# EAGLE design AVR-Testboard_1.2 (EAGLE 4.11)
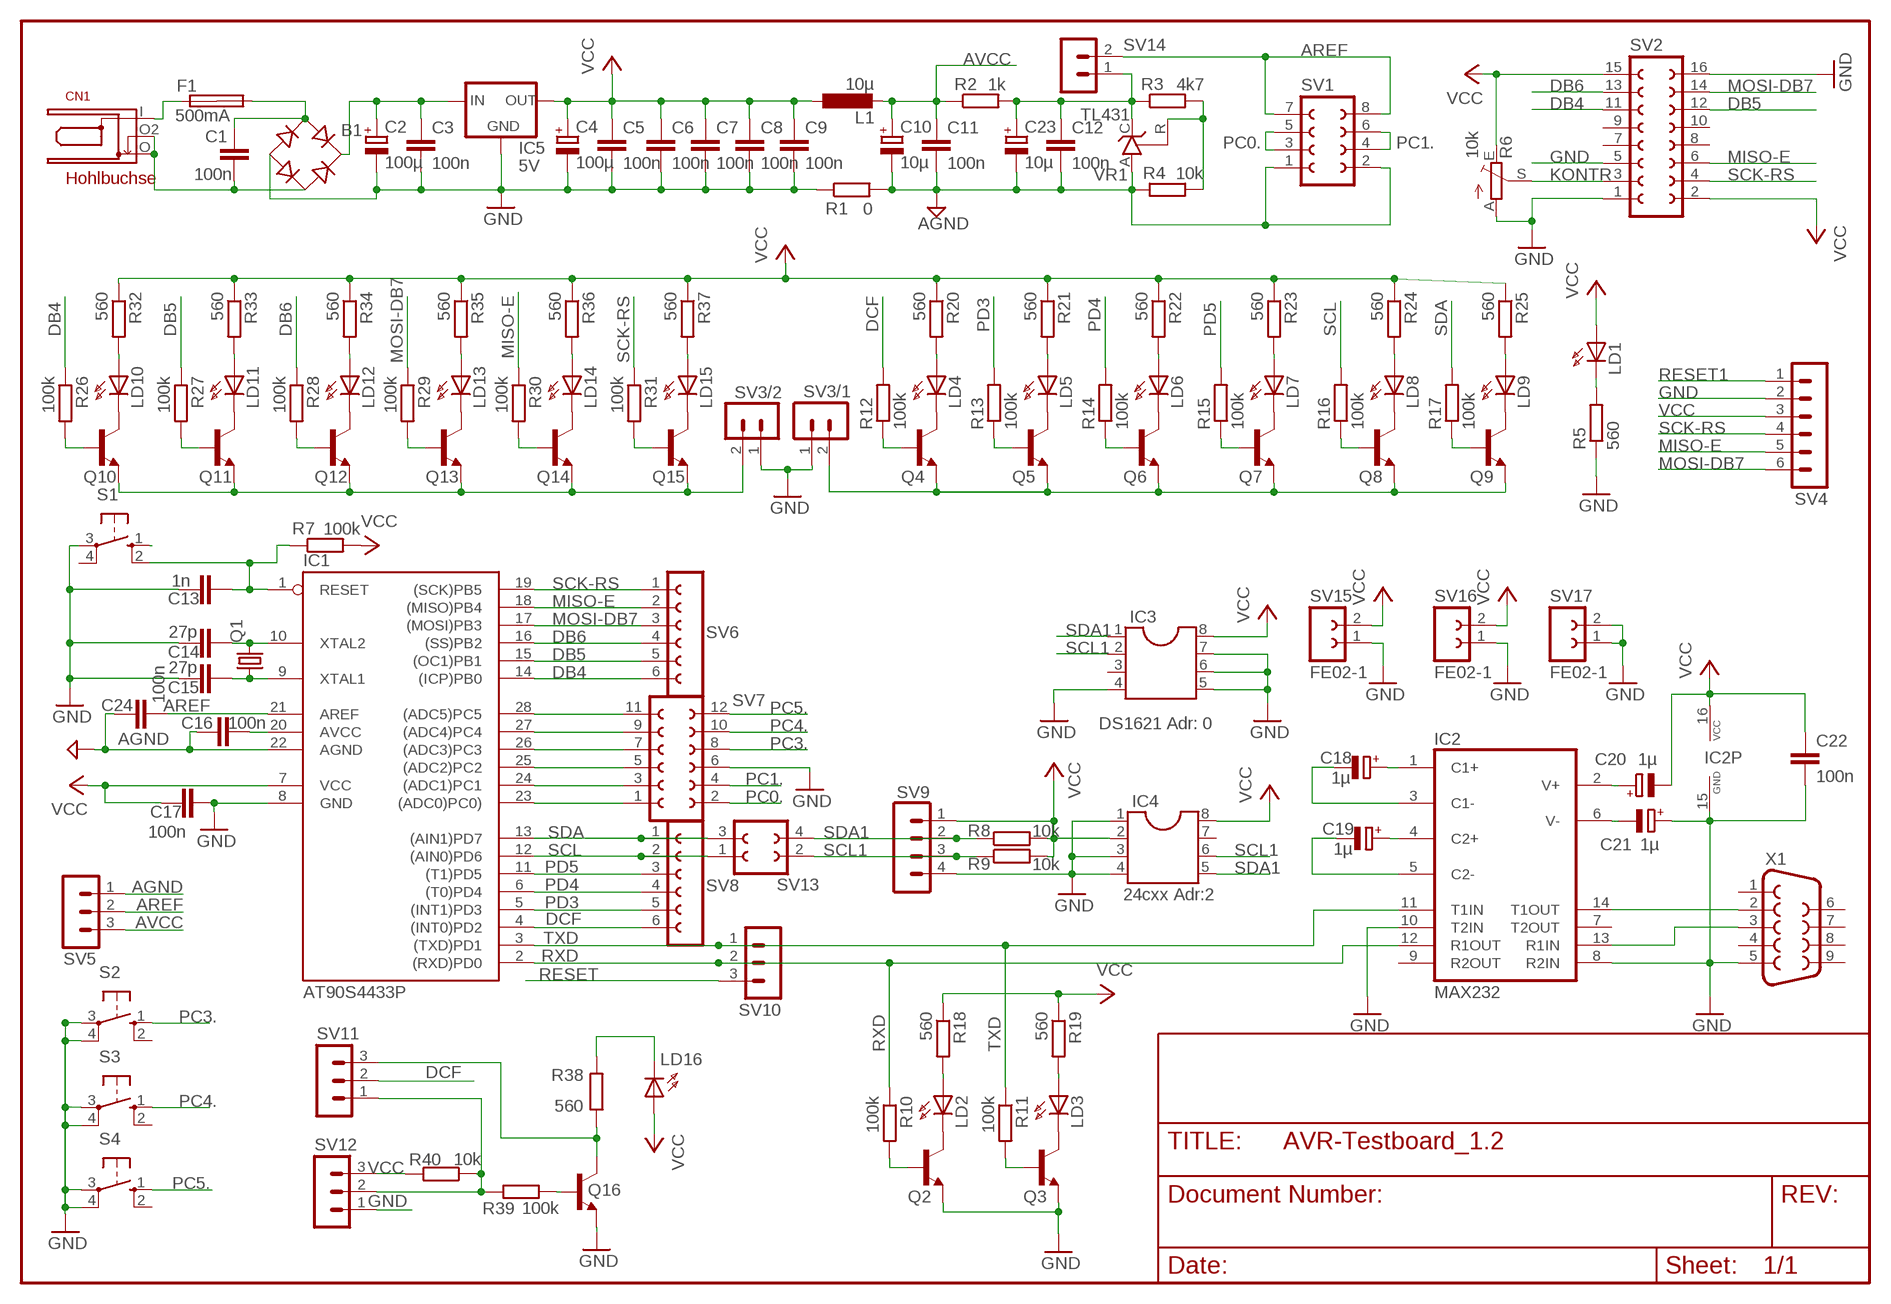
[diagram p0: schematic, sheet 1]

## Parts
B1  RB1A  [RB1A]
C1  100n  C-EU050-025X075  [C050-025X075]
C2  100µ  CPOL-EUE2.5-7  [E2,5-7]
C3  100n  C-EU050-025X075  [C050-025X075]
C4  100µ  CPOL-EUE2.5-7  [E2,5-7]
C5  100n  C-EU050-025X075  [C050-025X075]
C6  100n  C-EU050-025X075  [C050-025X075]
C7  100n  C-EU050-025X075  [C050-025X075]
C8  100n  C-EU050-025X075  [C050-025X075]
C9  100n  C-EU050-025X075  [C050-025X075]
C10  10µ  CPOL-EUE2.5-7  [E2,5-7]
C11  100n  C-EU050-025X075  [C050-025X075]
C12  100n  C-EU050-025X075  [C050-025X075]
C13  1n  C-EU050-025X075  [C050-025X075]
C14  27p  C-EU025-024X044  [C025-024X044]
C15  27p  C-EU025-024X044  [C025-024X044]
C16  100n  C-EU050-025X075  [C050-025X075]
C17  100n  C-EU050-025X075  [C050-025X075]
C18  1µ  CPOL-EUE2-5  [E2-5]
C19  1µ  CPOL-EUE2-5  [E2-5]
C20  1µ  CPOL-EUE2-5  [E2-5]
C21  1µ  CPOL-EUE2-5  [E2-5]
C22  100n  C-EU050-025X075  [C050-025X075]
C23  10µ  CPOL-EUE2.5-7  [E2,5-7]
C24  100n  C-EU050-025X075  [C050-025X075]
CN1  HOHLBUCHSE  [HOHLBUCHSE]
F1  500mA  SHK20L  [SHK20L]
IC1  AT90S4433P  [DIL28-3]
IC2  MAX232  [DIL16]
IC3  DIL8  [DIL08]
IC4  DIL8  [DIL08]
IC5  5V  78XXL  [78XXL]
L1  10µ  L-EU0204/5  [0204/5]
LD1  LED3MM  [LED3MM]
LD2  LED3MM  [LED3MM]
LD3  LED3MM  [LED3MM]
LD4  LED3MM  [LED3MM]
LD5  LED3MM  [LED3MM]
LD6  LED3MM  [LED3MM]
LD7  LED3MM  [LED3MM]
LD8  LED3MM  [LED3MM]
LD9  LED3MM  [LED3MM]
LD10  LED3MM  [LED3MM]
LD11  LED3MM  [LED3MM]
LD12  LED3MM  [LED3MM]
LD13  LED3MM  [LED3MM]
LD14  LED3MM  [LED3MM]
LD15  LED3MM  [LED3MM]
LD16  LED3MM  [LED3MM]
Q1  CRYTALHC18U-V  [HC18U-V]
Q2  BC548  [TO92-EBC]
Q3  BC548  [TO92-EBC]
Q4  BC548  [TO92-EBC]
Q5  BC548  [TO92-EBC]
Q6  BC548  [TO92-EBC]
Q7  BC548  [TO92-EBC]
Q8  BC548  [TO92-EBC]
Q9  BC548  [TO92-EBC]
Q10  BC548  [TO92-EBC]
Q11  BC548  [TO92-EBC]
Q12  BC548  [TO92-EBC]
Q13  BC548  [TO92-EBC]
Q14  BC548  [TO92-EBC]
Q15  BC548  [TO92-EBC]
Q16  BC548  [TO92-EBC]
R1  0  R-EU_0207/7  [0207/7]
R2  1k  R-EU_0204/7  [0204/7]
R3  4k7  R-EU_0204/7  [0204/7]
R4  10k  R-EU_0204/7  [0204/7]
R5  560  R-EU_0207/7  [0207/7]
R6  10k  TRIM_EU-PT10S  [PT-10S]
R7  100k  R-EU_0204/7  [0204/7]
R8  10k  R-EU_0204/7  [0204/7]
R9  10k  R-EU_0204/7  [0204/7]
R10  100k  R-EU_0204/7  [0204/7]
R11  100k  R-EU_0204/7  [0204/7]
R12  100k  R-EU_0207/15  [0207/15]
R13  100k  R-EU_0207/12  [0207/12]
R14  100k  R-EU_0207/12  [0207/12]
R15  100k  R-EU_0207/10  [0207/10]
R16  100k  R-EU_0204/7  [0204/7]
R17  100k  R-EU_0204/7  [0204/7]
R18  560  R-EU_0204/7  [0204/7]
R19  560  R-EU_0204/7  [0204/7]
R20  560  R-EU_0207/12  [0207/12]
R21  560  R-EU_0207/12  [0207/12]
R22  560  R-EU_0207/12  [0207/12]
R23  560  R-EU_0207/12  [0207/12]
R24  560  R-EU_0207/12  [0207/12]
R25  560  R-EU_0207/12  [0207/12]
R26  100k  R-EU_0207/15  [0207/15]
R27  100k  R-EU_0207/15  [0207/15]
R28  100k  R-EU_0207/15  [0207/15]
R29  100k  R-EU_0207/15  [0207/15]
R30  100k  R-EU_0207/15  [0207/15]
R31  100k  R-EU_0207/15  [0207/15]
R32  560  R-EU_0207/12  [0207/12]
R33  560  R-EU_0207/12  [0207/12]
R34  560  R-EU_0207/12  [0207/12]
R35  560  R-EU_0207/12  [0207/12]
R36  560  R-EU_0207/12  [0207/12]
R37  560  R-EU_0207/12  [0207/12]
R38  560  R-EU_0204/7  [0204/7]
R39  100k  R-EU_0204/7  [0204/7]
R40  10k  R-EU_0204/7  [0204/7]
S1  10-XX  [B3F-10XX]
S2  10-XX  [B3F-10XX]
S3  10-XX  [B3F-10XX]
S4  10-XX  [B3F-10XX]
SV1  FE04-2  [FE04-2]
SV2  FE08-2  [FE08-2]
SV3/1  MA02-1  [MA02-1]
SV3/2  MA02-1  [MA02-1]
SV4  MA06-1  [MA06-1]
SV5  MA03-1  [MA03-1]
SV6  FE06-1  [FE06]
SV7  FE06-2  [FE06-2]
SV8  FE06-1  [FE06]
SV9  MA04-1  [MA04-1]
SV10  MA03-1  [MA03-1]
SV11  MA03-1  [MA03-1]
SV12  MA03-1  [MA03-1]
SV13  FE02-2  [FE02-2]
SV14  MA02-1  [MA02-1]
SV15  FE02-1  [FE02-1]
SV16  FE02-1  [FE02-1]
SV17  FE02-1  [FE02-1]
VR1  TL431  TL431CLP  [TO92-CLP]
X1  F09H  [F09H]

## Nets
AGND: C10.- C11.2 C12.2 C16.1 C23.- C24.1 IC1.22(AGND) R1.2 R4.2 SV1.1 SV1.2 SV5.1 VR1.A
AREF: C24.2 IC1.21(AREF) SV1.7 SV1.8 SV5.2 SV14.2
AVCC: C10.+ C11.1 C16.2 IC1.20(AVCC) L1.2 R2.1 SV5.3
DB4: IC1.14((ICP)PB0) R26.1 SV2.11 SV6.6
DB5: IC1.15((OC1)PB1) R27.1 SV2.12 SV6.5
DB6: IC1.16((SS)PB2) R28.1 SV2.13 SV6.4
DCF: IC1.4((INT0)PD2) R12.2 SV8.6 SV11.2
GND: B1.- C2.- C3.2 C4.- C5.2 C6.2 C7.2 C8.2 C9.2 C13.1 C14.1 C15.1 C17.2 C21.+ C22.2 IC1.8(GND) IC2.8(R2IN) IC2.10(T2IN) IC2.15(GND) IC3.4 IC3.5 IC3.6 IC3.7 IC4.1 IC4.3 IC4.4 IC5.GND Q2.E Q3.E Q16.E R1.1 R5.1 R6.A S1.3(P) S2.3(P) S2.4(P1) S3.3(P) S3.4(P1) S4.3(P) S4.4(P1) SV2.1 SV2.5 SV2.16 SV3/1.1 SV3/2.1 SV4.2 SV7.6 SV9.4 SV12.1 SV15.1 SV16.1 SV17.1 SV17.2 X1.5
KONTR: R6.S SV2.3
MISO-E: IC1.18((MISO)PB4) R30.1 SV2.6 SV4.5 SV6.2
MOSI-DB7: IC1.17((MOSI)PB3) R29.1 SV2.14 SV4.6 SV6.3
N$1: C15.2 IC1.9(XTAL1) Q1.1
N$2: C14.2 IC1.10(XTAL2) Q1.2
N$3: CN1.I F1.2A
N$4: B1.+ C2.+ C3.1 IC5.IN
N$5: LD2.K(C) Q2.C
N$6: LD3.K(C) Q3.C
N$7: B1.AC1 C1.1 F1.1A
N$8: B1.AC2 C1.2 CN1.O CN1.O2
N$9: LD4.K(C) Q4.C
N$10: C20.+ IC2.2(V+)
N$11: C21.- IC2.6(V-)
N$12: C18.+ IC2.1(C1+)
N$13: C18.- IC2.3(C1-)
N$14: C19.+ IC2.4(C2+)
N$15: C19.- IC2.5(C2-)
N$16: LD5.K(C) Q5.C
N$17: Q16.C R38.1 SV11.3
N$18: LD6.K(C) Q6.C
N$19: LD9.K(C) Q9.C
N$20: LD8.K(C) Q8.C
N$21: LD7.K(C) Q7.C
N$22: LD2.A R18.2
N$23: LD3.A R19.2
N$24: R39.2 R40.1 SV11.1 SV12.2
N$25: LD4.A R20.2
N$26: LD5.A R21.2
N$27: LD6.A R22.2
N$28: LD7.A R23.2
N$29: LD8.A R24.2
N$30: LD9.A R25.2
N$31: LD10.K(C) Q10.C
N$32: Q4.E Q5.E Q6.E Q7.E Q8.E Q9.E SV3/1.2
N$33: LD11.K(C) Q11.C
N$34: LD12.K(C) Q12.C
N$35: LD13.K(C) Q13.C
N$36: LD14.K(C) Q14.C
N$37: LD11.A R33.2
N$38: LD12.A R34.2
N$39: LD13.A R35.2
N$40: Q10.B R26.2
N$41: Q11.B R27.2
N$42: Q12.B R28.2
N$43: Q13.B R29.2
N$44: LD14.A R36.2
N$45: LD15.K(C) Q15.C
N$46: LD15.A R37.2
N$47: Q2.B R10.2
N$48: LD16.K(C) R38.2
N$49: Q3.B R11.2
N$50: Q4.B R12.1
N$51: Q5.B R13.1
N$52: Q6.B R14.1
N$53: Q7.B R15.1
N$54: Q8.B R16.1
N$55: LD1.K(C) R5.2
N$56: Q9.B R17.1
N$57: LD10.A R32.2
N$58: C12.1 C23.+ R2.2 R3.1 SV14.1 VR1.C
N$59: Q14.B R30.2
N$60: Q15.B R31.2
N$61: Q10.E Q11.E Q12.E Q13.E Q14.E Q15.E SV3/2.2
N$62: IC2.14(T1OUT) X1.2
N$63: IC2.13(R1IN) X1.3
N$67: R3.2 R4.1 VR1.R
N$69: Q16.B R39.1
N$73: IC1.28((ADC5)PC5) SV7.11
N$74: IC1.27((ADC4)PC4) SV7.9
N$75: IC1.26((ADC3)PC3) SV7.7
N$76: IC1.25((ADC2)PC2) SV7.5
N$77: IC1.24((ADC1)PC1) SV7.3
N$78: IC1.23((ADC0)PC0)) SV7.1
PC0.: SV1.3 SV1.5 SV7.2
PC1.: SV1.4 SV1.6 SV7.4
PC3.: S2.1(S) SV7.8
PC4.: S3.1(S) SV7.10
PC5.: S4.1(S) SV7.12
PD3: IC1.5((INT1)PD3) R13.2 SV8.5
PD4: IC1.6((T0)PD4) R14.2 SV8.4
PD5: IC1.11((T1)PD5) R15.2 SV8.3
RESET: C13.2 IC1.1(RESET) R7.1 S1.2(S1) SV10.3
RESET1: S1.1(S) SV4.1
RXD: IC1.2((RXD)PD0) IC2.12(R1OUT) R10.1 SV10.2
SCK-RS: IC1.19((SCK)PB5) R31.1 SV2.4 SV4.4 SV6.1
SCL: IC1.12((AIN0)PD6) R16.2 SV8.2 SV13.1
SCL1: IC3.2 IC4.6 R9.1 SV9.3 SV13.2
SDA: IC1.13((AIN1)PD7) R17.2 SV8.1 SV13.3
SDA1: IC3.1 IC4.5 R8.1 SV9.2 SV13.4
TXD: IC1.3((TXD)PD1) IC2.11(T1IN) R11.1 SV10.1
VCC: C4.+ C5.1 C6.1 C7.1 C8.1 C9.1 C17.1 C20.- C22.1 IC1.7(VCC) IC2.16(VCC) IC3.8 IC4.2 IC4.8 IC5.OUT L1.1 LD1.A LD16.A R6.E R7.2 R8.2 R9.2 R18.1 R19.1 R20.1 R21.1 R22.1 R23.1 R24.1 R25.1 R32.1 R33.1 R34.1 R35.1 R36.1 R37.1 R40.2 SV2.2 SV2.15 SV4.3 SV9.1 SV12.3 SV15.2 SV16.2
Unconnected: F1.1B F1.2B IC2.7(T2OUT) IC2.9(R2OUT) IC3.3 IC4.7 S1.4(P1) S2.2(S1) S3.2(S1) S4.2(S1) SV2.7 SV2.8 SV2.9 SV2.10 X1.1 X1.4 X1.6 X1.7 X1.8 X1.9

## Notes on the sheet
- DS1621 Adr: 0
- 24cxx Adr:2

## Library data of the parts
B1 = rectifier:RB1A: RECTIFIER 1 A
C1 C3 C5-C9 C11-C17 C22 C24 = rcl:C-EU: CAPACITOR, European symbol
C2 C4 C10 C18-C21 C23 = rcl:CPOL-EU: POLARIZED CAPACITOR, European symbol
CN1 = Ergaenzung:HOHLBUCHSE
F1 = fuse:SHK20L: FUSE HOLDER 5 x 20 mm, SH contact, SHH1 Schukat, E1073 Buerklin
IC1 = atmel:AT90S4433: MICROCONTROLLER 4 Kbytes FLASH 128 bytes SRAM 256 bytes EEPROM UART 6-channel 10 bit ADC
IC2 = maxim:MAX232: RS232 TRANSEIVER
IC3 IC4 = dil:DIL8: SOCKET Dual In Line
IC5 = v-reg:78XXL: VOLTAGE REGULATOR
L1 = rcl:L-EU: INDUCTOR, European symbol
LD1-LD16 = led:LED: LED
Q1 = crystal:CRYTAL: CRYSTAL
Q2-Q16 = transistor-npn:BC548*: NPN Transistor
R1-R5 R7-R11 R18-R40 = rcl:R-EU_: RESISTOR, European symbol
R6 = pot:TRIM_EU-: POTENTIOMETER
R12-R17 = rcl-E:R-EU_: RESISTOR, European symbol
S1-S4 = switch-omron:10-XX: OMRON SWITCH
SV1 = con-lsta-E:FE04-2: FEMALE-PINHEADER
SV2 = con-lsta:FE08-2: FEMALE HEADER
SV3/1 SV3/2 SV14 = con-lstb-E:MA02-1
SV4 = con-lstb:MA06-1: PIN HEADER
SV5 SV10-SV12 = con-lstb:MA03-1: PIN HEADER
SV6 SV8 = con-lsta:FE06-1: FEMALE HEADER
SV7 = con-lsta:FE06-2: FEMALE HEADER
SV9 = con-lstb:MA04-1: PIN HEADER
SV13 = con-lsta-E:FE02-2: FEMALE-PINHEADER
SV15-SV17 = con-lsta-E:FE02-1: FEMALE-PINHEAD
VR1 = v-reg:TL431CLP: VOLTAGE REGULATOR
X1 = con-subd:F09: SUB-D

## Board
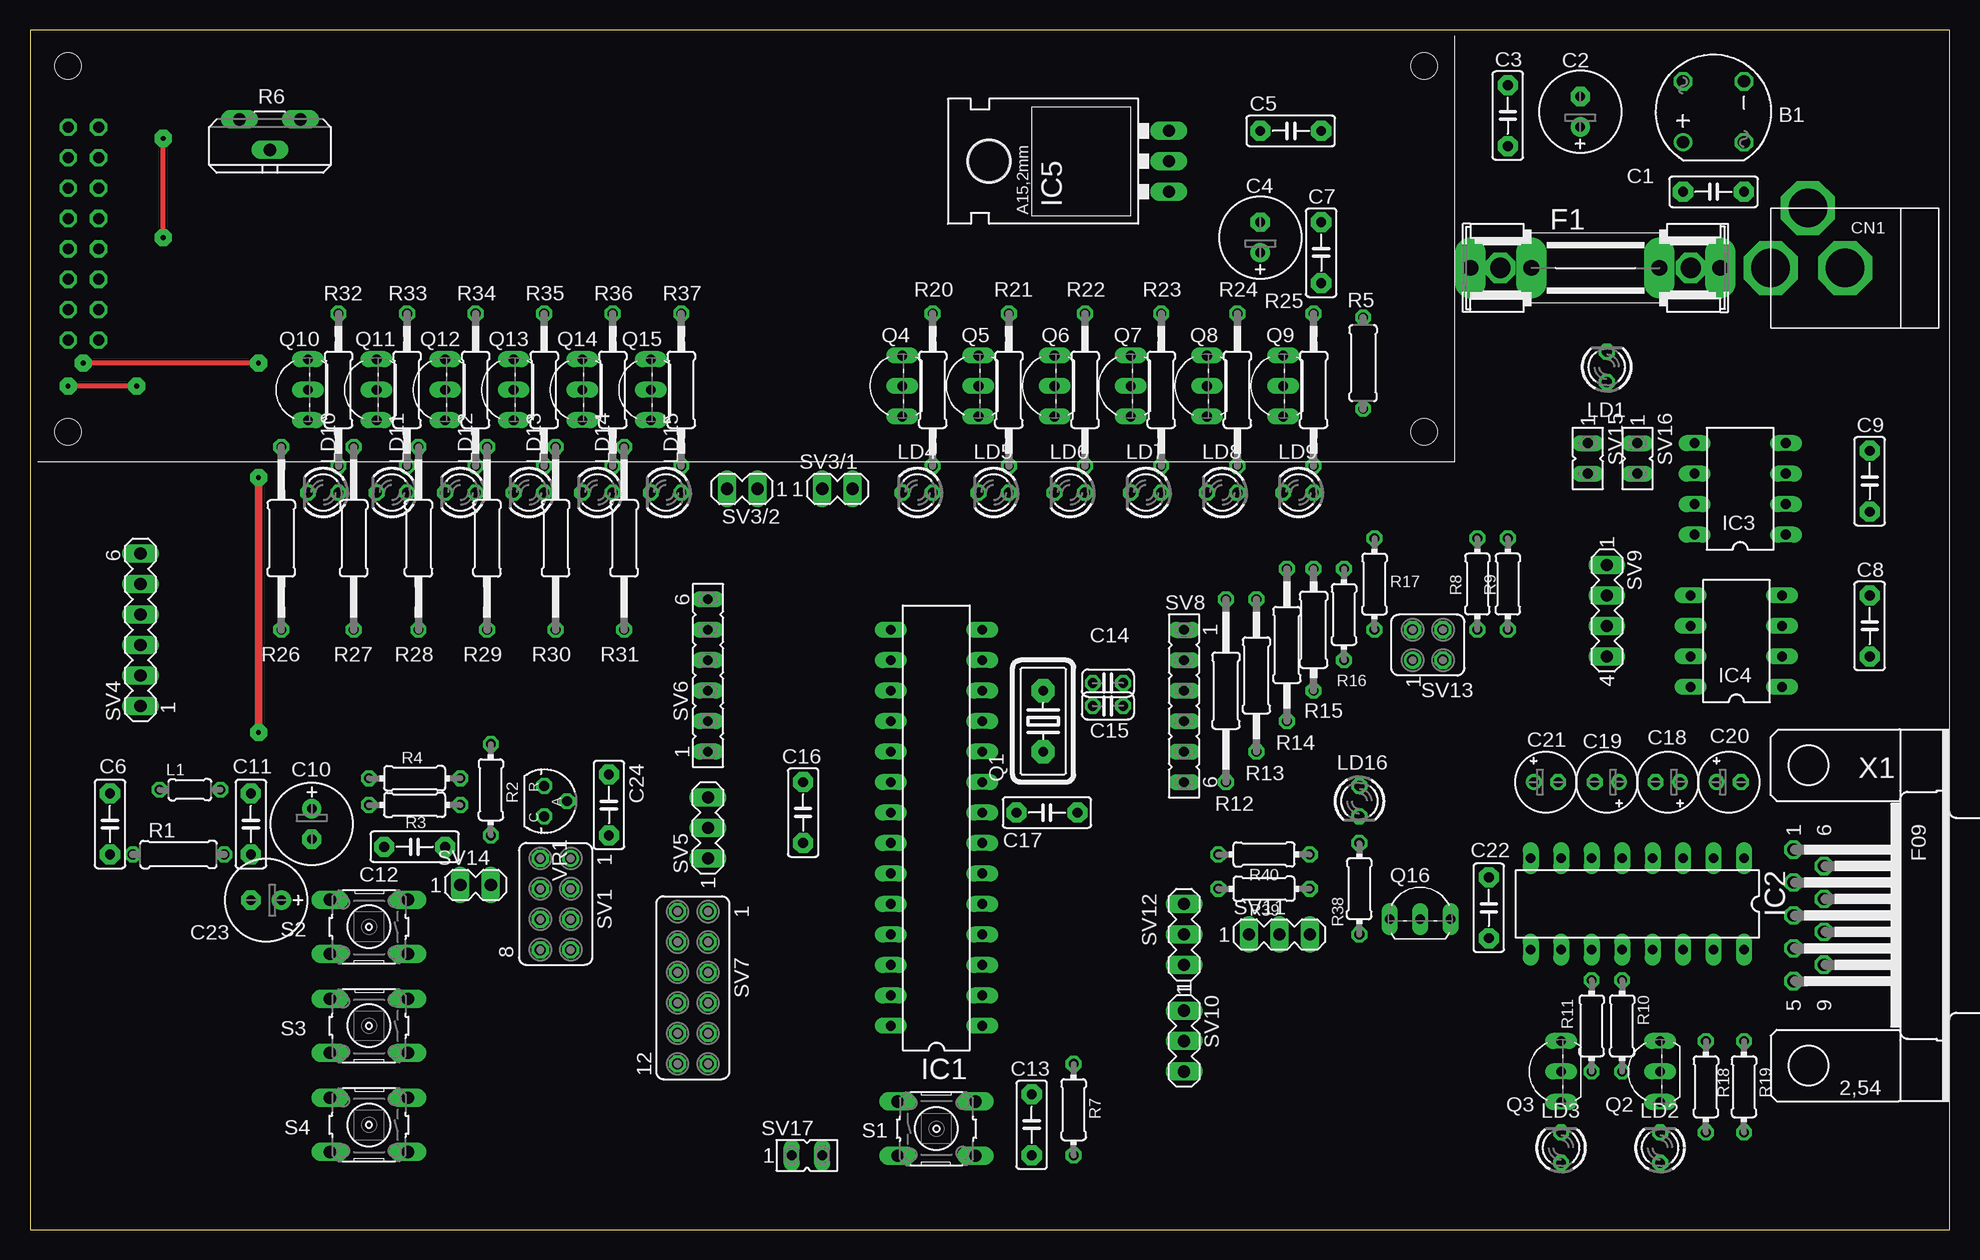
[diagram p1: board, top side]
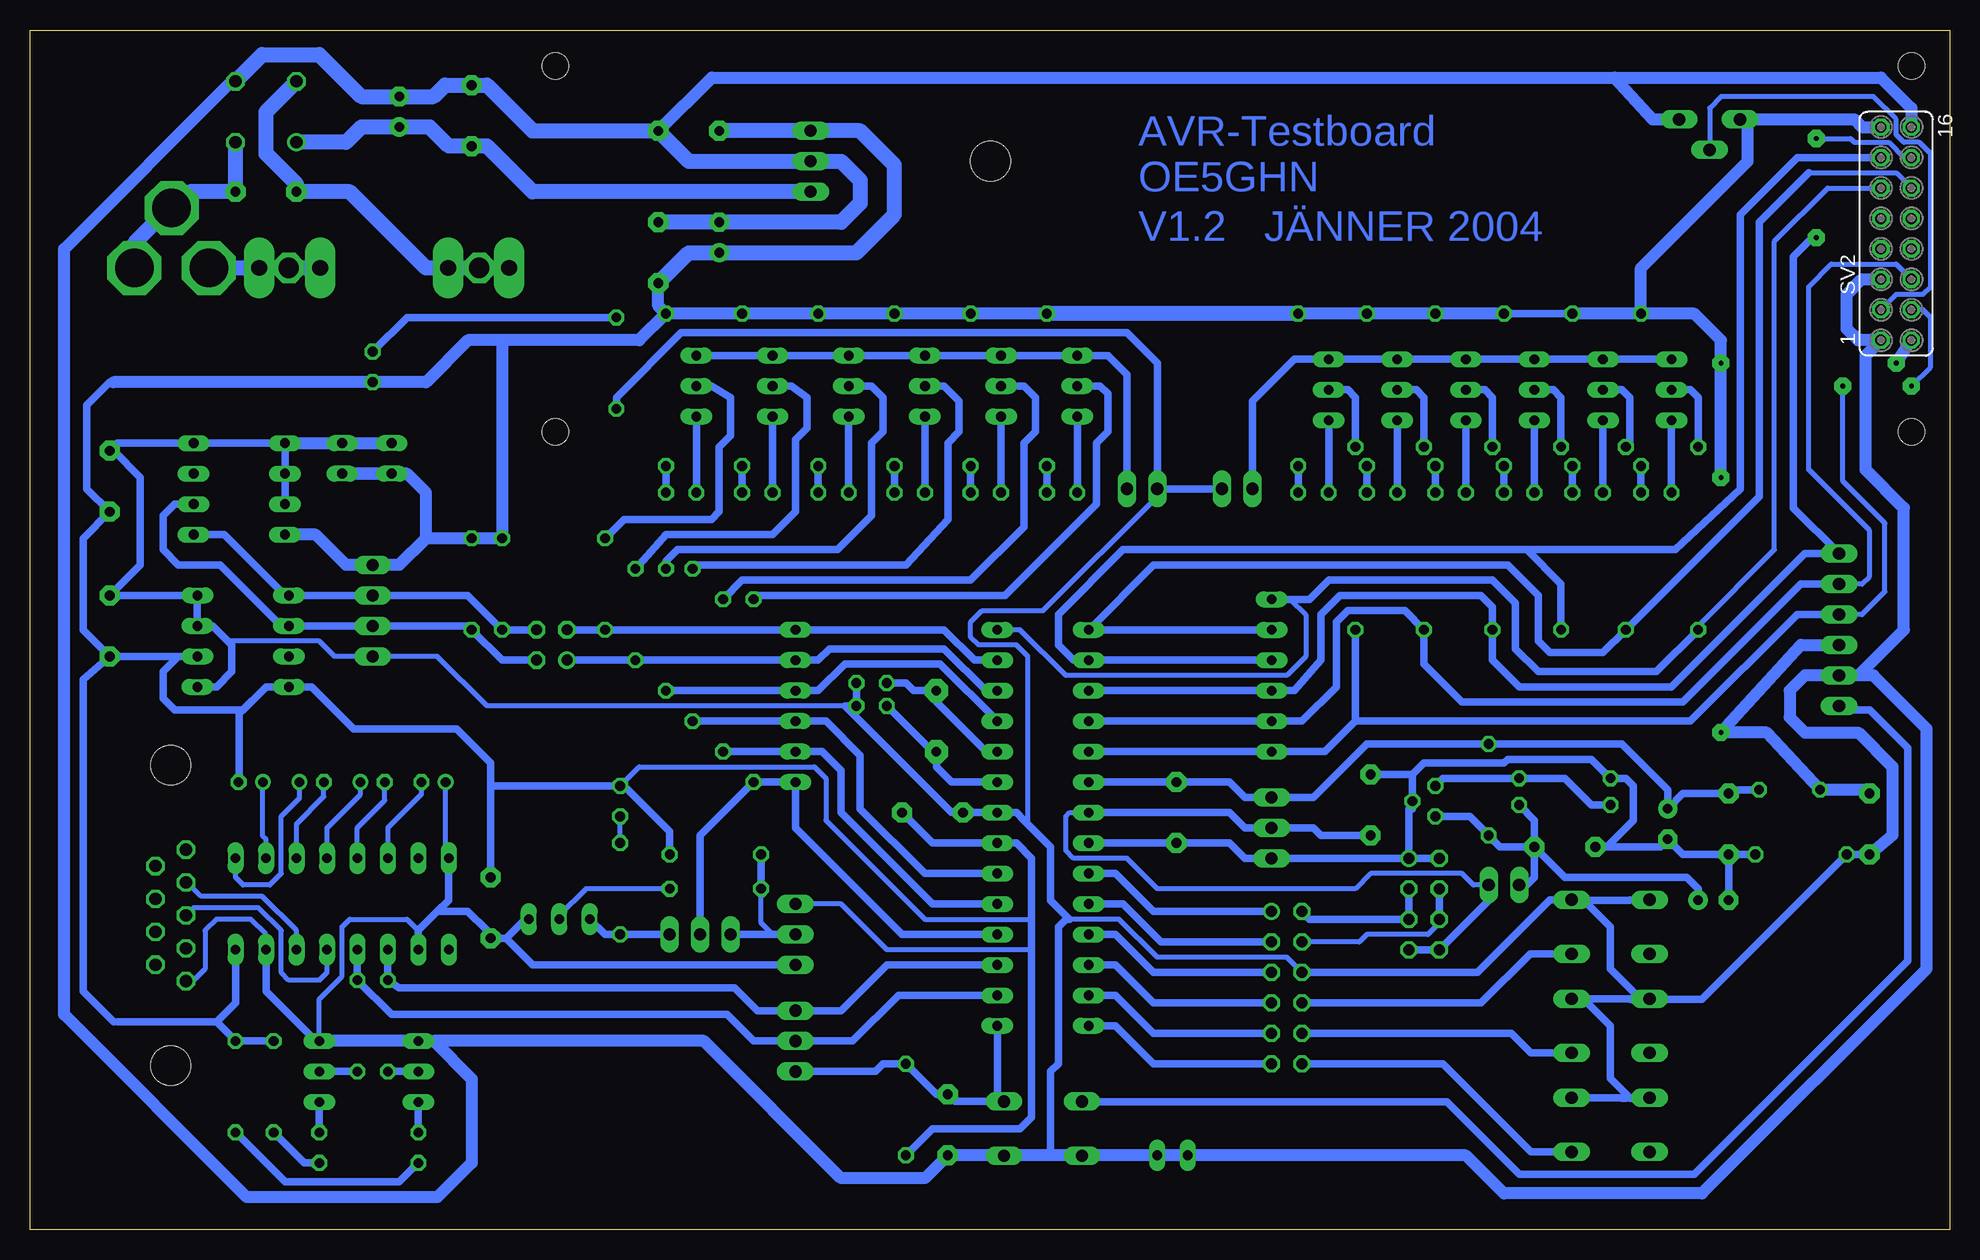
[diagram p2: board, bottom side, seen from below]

Size 160 x 100 mm. Coordinates in mm from the lower left corner, seen from the top.
Outline: 0,0 160,0 160,100 0,100 0,0
Copper layers (1*16): Top 0.035mm / dielectric 1.5mm / Bottom 0.035mm
Design rules "default": minimum track width 16mil, minimum drill 24mil, track to track 8mil, track to pad 8mil, pad to pad 8mil, via to via 8mil, smd to smd 8mil, copper to edge 40mil, drill to drill 20mil, minimum pad ring 10mil, minimum via ring 8mil, stop-mask expansion 4mil, vias tented up to drill 0mil, thermal gap 10mil
Holes 2.18 mm at 3.17,66.51 116.2,66.51 116.2,96.99 3.17,96.99

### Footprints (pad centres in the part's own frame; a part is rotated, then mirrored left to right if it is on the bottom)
RB1A = drill 1.016 round: + -2.54,2.54 | drill 1.016 octagon: - 2.54,-2.54; AC1 2.54,2.54; AC2 -2.54,-2.54
C050-025X075 = drill 0.813 pad 1.676 octagon: 1 -2.54,0; 2 2.54,0
E2,5-7 = drill 0.813 pad 1.6 round: + -1.27,0 | drill 0.813 pad 1.6 octagon: - 1.27,0
C025-024X044 = drill 0.813 octagon: 1 -1.27,0; 2 1.27,0
E2-5 = drill 0.813 pad 1.27 round: + -1.016,0 | drill 0.813 pad 1.27 octagon: - 1.016,0
HOHLBUCHSE = drill 3.2 pad 4.5 octagon: I 0,0; O 6.2,0; O2 3.1,5
SHK20L = drill 1.321 pad 2.54 long: 1A -10.414,0; 1B -5.334,0; 2A 10.414,0; 2B 5.334,0
DIL28-3 = drill 0.813 long: 1 -16.51,-3.81; 2 -13.97,-3.81; 3 -11.43,-3.81; 4 -8.89,-3.81; 5 -6.35,-3.81; 6 -3.81,-3.81; 7 -1.27,-3.81; 8 1.27,-3.81; 9 3.81,-3.81; 10 6.35,-3.81; 11 8.89,-3.81; 12 11.43,-3.81; 13 13.97,-3.81; 14 16.51,-3.81; 15 16.51,3.81; 16 13.97,3.81; 17 11.43,3.81; 18 8.89,3.81; 19 6.35,3.81; 20 3.81,3.81; 21 1.27,3.81; 22 -1.27,3.81; 23 -3.81,3.81; 24 -6.35,3.81; 25 -8.89,3.81; 26 -11.43,3.81; 27 -13.97,3.81; 28 -16.51,3.81
DIL16 = drill 0.813 long: 1 -8.89,-3.81; 2 -6.35,-3.81; 3 -3.81,-3.81; 4 -1.27,-3.81; 5 1.27,-3.81; 6 3.81,-3.81; 7 6.35,-3.81; 8 8.89,-3.81; 9 8.89,3.81; 10 6.35,3.81; 11 3.81,3.81; 12 1.27,3.81; 13 -1.27,3.81; 14 -3.81,3.81; 15 -6.35,3.81; 16 -8.89,3.81
DIL08 = drill 0.813 long: 1 -3.81,-3.81; 2 -1.27,-3.81; 3 1.27,-3.81; 4 3.81,-3.81; 5 3.81,3.81; 6 1.27,3.81; 7 -1.27,3.81; 8 -3.81,3.81
78XXL = drill 1.016 long: GND 0,-3.81; IN -2.54,-3.81; OUT 2.54,-3.81 | hole 3.302: 0,11.176
0204/5 = drill 0.813 octagon: 1 -2.54,0; 2 2.54,0
LED3MM = drill 0.813 octagon: A -1.27,0; K 1.27,0
HC18U-V = drill 0.813 pad 1.93 octagon: 1 -2.54,0; 2 2.54,0
TO92-EBC = drill 0.813 long: B 0,-1.27; C -2.54,-1.27; E 2.54,-1.27
0207/7 = drill 0.813 octagon: 1 -3.81,0; 2 3.81,0
0204/7 = drill 0.813 octagon: 1 -3.81,0; 2 3.81,0
PT-10S = drill 1.016 long: A -2.54,-1.27; E 2.54,-1.27; S 0,1.27
0207/15 = drill 0.813 octagon: 1 -7.62,0; 2 7.62,0
0207/12 = drill 0.813 octagon: 1 -6.35,0; 2 6.35,0
0207/10 = drill 0.813 octagon: 1 -5.08,0; 2 5.08,0
B3F-10XX = drill 1.016 long: 1 -3.251,2.261; 2 3.251,2.261; 3 -3.251,-2.261; 4 3.251,-2.261
FE04-2 = drill 0.914 round: 1 -3.81,1.27 | drill 0.914 octagon: 2 -3.81,-1.27; 3 -1.27,1.27; 4 -1.27,-1.27; 5 1.27,1.27; 6 1.27,-1.27; 7 3.81,1.27; 8 3.81,-1.27
FE08-2 = drill 0.914 octagon: 1 -8.89,1.27; 2 -8.89,-1.27; 3 -6.35,1.27; 4 -6.35,-1.27; 5 -3.81,1.27; 6 -3.81,-1.27; 7 -1.27,1.27; 8 -1.27,-1.27; 9 1.27,1.27; 10 1.27,-1.27; 11 3.81,1.27; 12 3.81,-1.27; 13 6.35,1.27; 14 6.35,-1.27; 15 8.89,1.27; 16 8.89,-1.27
MA02-1 = drill 1.016 long: 1 -1.27,0; 2 1.27,0
MA06-1 = drill 1.016 long: 1 -6.35,0; 2 -3.81,0; 3 -1.27,0; 4 1.27,0; 5 3.81,0; 6 6.35,0
MA03-1 = drill 1.016 long: 1 -2.54,0; 2 0,0; 3 2.54,0
FE06 = drill 0.813 long: 1 -6.35,0; 2 -3.81,0; 3 -1.27,0; 4 1.27,0; 5 3.81,0; 6 6.35,0
FE06-2 = drill 0.914 round: 1 -6.35,1.27 | drill 0.914 octagon: 2 -6.35,-1.27; 3 -3.81,1.27; 4 -3.81,-1.27; 5 -1.27,1.27; 6 -1.27,-1.27; 7 1.27,1.27; 8 1.27,-1.27; 9 3.81,1.27; 10 3.81,-1.27; 11 6.35,1.27; 12 6.35,-1.27
MA04-1 = drill 1.016 long: 1 -3.81,0; 2 -1.27,0; 3 1.27,0; 4 3.81,0
FE02-2 = drill 0.914 round: 1 -1.27,1.27 | drill 0.914 octagon: 2 -1.27,-1.27; 3 1.27,1.27; 4 1.27,-1.27
FE02-1 = drill 0.813 long: 1 -1.27,0; 2 1.27,0
TO92-CLP = drill 0.813 octagon: A 0,1.905; C 1.27,0; R -1.27,0
F09H = drill 1.016 octagon: 1 -5.486,-1.27; 2 -2.743,-1.27; 3 0,-1.27; 4 2.743,-1.27; 5 5.486,-1.27; 6 -4.115,1.27; 7 -1.372,1.27; 8 1.372,1.27; 9 4.115,1.27 | hole 3.302: -12.522,0; 12.522,0

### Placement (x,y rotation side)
B1  140.33,93.18 90 top
C1  140.33,86.51 0 top
C2  129.22,93.18 90 top
C3  123.19,92.86 90 top
C4  102.55,82.7 90 top
C5  105.09,91.59 0 top
C6  6.66,33.81 270 top
C7  107.63,81.43 90 top
C8  153.35,50.32 90 top
C9  153.35,62.38 90 top
C10  23.49,33.81 270 top
C11  18.41,33.81 270 top
C12  32.06,31.9 180 top
C13  83.5,8.73 90 top
C14  89.85,45.55 180 top
C15  89.85,43.65 180 top
C16  64.45,34.76 90 top
C17  84.77,34.76 180 top
C18  136.52,37.3 180 top
C19  131.44,37.3 180 top
C20  141.6,37.3 0 top
C21  126.36,37.3 0 top
C22  121.6,26.82 270 top
C23  19.68,27.46 180 top
C24  48.26,35.39 270 top
CN1  145.09,80.16 0 top
F1  130.49,80.16 0 top
IC1  75.56,33.49 90 top
IC2  133.98,27.14 180 top
IC3  142.55,61.75 90 top
IC4  142.23,49.05 90 top
IC5  91.12,89.05 90 top
L1  13.33,36.66 0 top
LD1  131.44,71.91 90 top
LD2  135.88,6.82 90 top
LD3  127.63,6.82 90 top
LD4  73.97,61.43 180 top
LD5  80.32,61.43 180 top
LD6  86.67,61.43 180 top
LD7  93.02,61.43 180 top
LD8  99.37,61.43 180 top
LD9  105.72,61.43 180 top
LD10  24.44,61.43 180 top
LD11  30.16,61.43 180 top
LD12  35.87,61.43 180 top
LD13  41.59,61.43 180 top
LD14  47.3,61.43 180 top
LD15  53.02,61.43 180 top
LD16  110.8,35.71 270 top
Q1  84.45,42.38 90 top
Q2  134.62,13.17 90 top
Q3  126.36,13.17 90 top
Q4  71.43,70.32 90 top
Q5  77.78,70.32 90 top
Q6  84.13,70.32 90 top
Q7  90.48,70.32 90 top
Q8  96.83,70.32 90 top
Q9  103.18,70.32 90 top
Q10  21.9,70 90 top
Q11  27.62,70 90 top
Q12  33.33,70 90 top
Q13  39.05,70 90 top
Q14  44.76,70 90 top
Q15  50.48,70 90 top
Q16  115.88,27.14 0 top
R1  12.38,31.27 0 top
R2  38.41,36.66 270 top
R3  32.06,35.39 180 top
R4  32.06,37.62 180 top
R5  111.12,72.22 90 top
R6  20,91.28 180 top
R7  86.99,10 270 top
R8  120.64,53.81 90 top
R9  123.19,53.81 90 top
R10  132.71,16.98 270 top
R11  130.17,16.98 270 top
R12  99.69,44.92 270 top
R13  102.23,46.19 270 top
R14  104.77,48.73 270 top
R15  106.99,50 270 top
R16  109.53,51.27 270 top
R17  112.07,53.81 270 top
R18  139.69,11.9 270 top
R19  142.87,11.9 270 top
R20  75.24,70 270 top
R21  81.59,70 270 top
R22  87.94,70 270 top
R23  94.29,70 270 top
R24  100.64,70 270 top
R25  106.99,70 270 top
R26  20.95,57.62 90 top
R27  26.98,57.62 90 top
R28  32.38,57.62 90 top
R29  38.1,57.62 90 top
R30  43.81,57.62 90 top
R31  49.53,57.62 90 top
R32  25.71,70 270 top
R33  31.43,70 270 top
R34  37.14,70 270 top
R35  42.86,70 270 top
R36  48.57,70 270 top
R37  54.29,70 270 top
R38  110.8,28.41 90 top
R39  102.86,28.41 180 top
R40  102.86,31.27 0 top
S1  75.56,8.41 0 top
S2  28.25,25.23 180 top
S3  28.25,16.98 180 top
S4  28.25,8.73 180 top
SV1  43.81,27.14 270 top
SV2  4.44,83.02 90 bottom
SV3/1  67.3,61.75 0 top
SV3/2  59.37,61.75 180 top
SV4  9.2,50 90 top
SV5  56.51,33.49 90 top
SV6  56.51,46.19 90 top
SV7  55.24,20.15 270 top
SV8  96.2,43.65 270 top
SV9  131.44,51.59 270 top
SV10  96.2,15.71 270 top
SV11  104.13,24.6 0 top
SV12  96.2,24.6 90 top
SV13  116.52,48.73 90 top
SV14  37.14,28.73 0 top
SV15  129.85,64.29 270 top
SV16  133.98,64.29 270 top
SV17  64.77,6.18 0 top
VR1  42.86,35.71 270 top
X1  148.27,26.19 270 top

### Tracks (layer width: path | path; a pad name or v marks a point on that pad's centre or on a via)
AGND
  Bottom 0.61: SV1.1 SV1.2 | C11.2 R1.2 | C11.2 22.22,31.27 C10.- 24.12,31.9 C12.2 28.57,31.9 26.35,34.12 26.35,36.98 26.98,37.62 R4.2 29.84,39.2 36.83,39.2 37.14,38.89 43.81,38.89 44.76,37.94 | 44.76,37.94 VR1.A 44.76,35.08 45.08,35.08 SV1.1 | IC1.22 C16.1 60,32.22 58.73,30.95 SV5.1 SV1.1 | C23.- C11.2 | 44.76,37.94 C24.1
AREF
  Bottom 0.406: IC1.21 73.34,34.76 73.66,34.44 73.66,31.58 73.02,30.95 68.57,30.95 66.03,28.41 49.53,28.41 48.26,29.68 40.64,29.68 39.68,28.73 SV14.2
  Bottom 0.61: IC1.21 60,34.76 58.73,33.49 SV5.2 53.02,33.49 52.38,32.85 C24.2 | SV1.7 SV1.8 38.41,27.46 SV14.2
AVCC
  Bottom 0.61: 56.83,36.03 58.73,36.03 60,37.3 C16.2 IC1.20 | L1.2 18.09,36.66 C11.1 22.22,36.35 C10.+ 23.49,36.66 27.3,40.48 R2.1 48.57,40.48 53.02,36.03 56.83,36.03 | 56.83,36.03 SV5.3
DB4
  Bottom 0.406: IC1.14 77.46,50 73.66,46.19 55.24,46.19 53.65,47.78 53.65,51.27 54.92,52.54 SV6.6 | 20.95,50.32 14.6,56.67 14.6,82.39 10.16,86.83 SV2.11
  Bottom 0.61: SV6.6 53.34,52.54 51.75,54.13 38.1,54.13 36.19,52.22 36.19,48.41 34.29,46.51 24.44,46.51 R26.1 20.95,50.32
DB5
  Bottom 0.406: 11.74,88.1 4.44,88.1 SV2.12
  Bottom 0.61: SV6.5 IC1.15 66.35,55.4 36.83,55.4 34.29,52.86 34.29,49.05 33.33,48.09 28.89,48.09 R27.1 15.87,61.11 15.87,83.97 11.74,88.1
DB6
  Bottom 0.61: 35.24,56.67 32.38,53.81 R28.1 | 35.24,56.67 22.86,56.67 17.46,61.75 17.46,84.61 12.7,89.37 SV2.13 | 35.24,56.67 68.89,56.67 74.29,51.27 74.29,48.73 73.02,47.46 IC1.16 SV6.4
DCF
  Bottom 0.61: IC1.4 87.31,24.6 96.2,33.49 SV8.6 R12.2 104.13,32.85 SV11.2
GND
  Bottom 0.406: SV4.2 7.62,46.19 | 73.34,25.87 69.21,25.87 66.03,22.7 55.24,22.7 SV7.6 | IC2.8 125.09,31.27 125.34,31.52 C21.+ | IC2.15 140.33,24.6 141.6,25.87 144.46,25.87 145.41,24.92 145.41,21.74 146.45,20.7 X1.5 | 127.63,24.92 128.58,25.87 133.34,25.87 133.98,25.23 133.98,21.11 135.88,19.2 Q2.E | 143.5,49.05 135.88,49.05 134.62,47.78 SV9.4 126.04,47.78 121.91,43.65 92.07,43.65 | 66.03,61.11 75.56,51.59 80.64,51.59 81.59,50.63 81.59,49.37 80.96,48.73 77.78,48.73 76.83,47.78 76.83,34.12 77.15,34.12 | 143.19,95.72 B1.-
  Bottom 0.61: IC4.1 144.46,45.24 143.19,46.51 143.19,48.73 143.5,49.05 144.78,50.32 IC4.3 146.36,50.32 146.04,50.63 IC4.4 C8.2 150.81,55.4 150.81,62.7 153.03,64.92 C9.2 152.71,65.56 IC3.4 | SV12.1 118.1,22.06 120.33,24.28 | 120.33,24.28 C22.2 121.91,23.96 121.91,24.92 123.5,26.5 126.04,26.5 | R5.1 111.12,69.37 105.72,74.77 68.57,74.77 66.03,72.22 SV3/1.1 | 89.21,40.79 83.18,34.76 C17.2 IC1.8 77.78,34.76 77.15,34.12 74.92,31.9 74.92,27.46 73.34,25.87 73.66,25.87 74.29,25.23 74.29,13.81 74.92,13.17 74.92,6.18 | 89.21,40.79 89.66,41.24 | 126.04,26.5 127.63,24.92 IC2.10 127.31,23.01 | IC2.8 125.09,27.46 126.04,26.5 | Q2.E 136.2,15.71 140.33,19.84 IC2.15 | 89.21,40.79 92.07,43.65 C15.1 C14.1 | C6.2 R1.1 20.63,19.2 25.71,19.2 | IC3.7 IC3.6 IC3.5 IC3.4 | IC3.4 146.68,65.56 | 126.36,15.71 Q3.E | S2.4 26.63,27.5 26.66,27.46 30.47,27.46 | Q16.E 118.74,25.87 120.33,24.28 | C13.1 83.46,6.15 | S3.3 32.42,19.24 | 26.66,10.99 26.94,10.99 26.98,10.95 27.3,10.95 | 26.63,10.99 S4.4 | 26.63,10.99 26.66,10.99 | S2.3 32.74,27.5 | 26.66,19.2 26.63,19.24 | 26.66,10.99 S4.3 | 26.66,10.95 26.35,10.95 | 26.66,19.2 26.66,19.24 | S2.3 33.29,27.5 39.37,21.42 SV7.6 | 73.69,6.15 S1.3 72.35,6.15 72.38,6.18 | 26.66,10.99 26.66,10.95 | 26.63,10.99 26.66,10.95 | SV3/1.1 66.35,61.75 | 66.03,61.11 SV3/1.1 | SV3/1.1 SV3/2.1 | 26.66,19.2 26.35,19.2 26.39,19.24 S3.3 | S3.4 25.71,19.24 25.75,19.24 28.25,21.74 28.25,25.23 30.47,27.46 | S2.3 31.47,27.5 30.47,27.46 | 26.63,10.99 28.25,12.61 28.25,16.98 30.47,19.2 31.47,19.2 S3.3
  Bottom 0.813: 25.71,19.24 25.71,19.2 26.35,19.2
  Bottom 1.016: 7.62,46.19 3.8,50 3.8,60.16 6.98,63.34 6.98,72.86 SV2.1 7.62,74.13 8.57,75.08 8.57,77.94 7.3,79.21 SV2.5 | Q3.E Q2.E | C6.2 4.76,32.85 4.76,38.57 7.62,41.43 12.06,41.43 13.33,42.7 13.33,44.92 12.06,46.19 SV4.2 6.34,46.19 1.9,41.74 1.9,21.74 20.63,3.01 37.14,3.01 40.32,6.18 SV17.1 | 143.19,95.72 157.16,81.75 157.16,17.93 141.92,2.69 126.04,2.69 123.19,5.55 123.19,12.54 126.36,15.71 103.82,15.71 92.39,4.28 85.4,4.28 C13.1 72.38,6.18 SV17.2 | SV17.1 SV17.2 | 27.93,96.04 103.18,96.04 C5.2 | 27.93,96.04 24.76,92.55 R6.A | SV2.16 3.17,93.5 5.71,96.04 27.93,96.04 | IC3.5 SV16.1 SV15.1 | SV17.1 SV17.2
  Bottom 1.27: B1.- 140.65,97.94 135.88,97.94 132.39,94.45 C2.- 126.36,94.45 125.41,95.4 C3.2 121.91,95.4 118.1,91.59 C5.2 105.09,89.05 IC5.GND 92.39,89.05 90.8,87.47 90.8,85.56 92.39,83.97 C4.- C7.2
KONTR
  Bottom 0.406: R6.S 20,93.5 19.04,94.45 6.34,94.45 4.44,92.55 4.44,91.28 3.8,90.64 2.54,90.64 1.58,89.69 1.58,78.58 2.22,77.94 4.44,77.94 SV2.3
MISO-E
  Bottom 0.406: SV4.5 7.3,53.81 6.66,54.45 6.66,58.25 11.74,63.34 11.74,78.58 9.84,80.48 4.44,80.48 SV2.6
  Bottom 0.61: IC1.18 SV6.2 53.97,42.38 51.11,45.24 51.11,50.63 50.16,51.59 45.4,51.59 R30.1 43.81,47.14 40.64,43.97 22.22,43.97 12.38,53.81 SV4.5
MOSI-DB7  (via drill 0.41 pad 1.42)
  Top 0.406: v11.11,82.7 v11.11,90.96
  Bottom 0.406: 11.11,83.02 v11.11,82.7 | v11.11,90.96 8.25,90.96 7.93,90.64 5.08,90.64 3.8,89.37 SV2.14
  Bottom 0.61: IC1.17 SV6.3 54.61,44.92 52.38,47.46 52.38,51.27 50.8,52.86 39.05,52.86 38.1,51.91 R29.1 38.1,47.46 35.87,45.24 23.17,45.24 12.06,56.35 SV4.6 13.01,60.16 13.01,81.11 11.11,83.02
N$1
  Bottom 0.61: IC1.9 83.18,37.3 84.45,38.57 Q1.1 84.77,39.84 C15.2
N$2
  Bottom 0.61: IC1.10 80.32,39.84 84.45,43.97 Q1.2 86.35,44.92 86.99,45.55 C14.2
N$3  (via drill 1.68)
  Bottom 1.016: 140.97,80.16 F1.2A
  Bottom 1.27: CN1.I 140.97,80.16 v138.42,80.16 135.88,80.16
N$4
  Bottom 1.27: B1.+ 133.66,90.64 132.39,91.91 C2.+ 126.68,91.91 125.09,90.32 C3.1 121.91,90.32 118.1,86.51 IC5.IN
N$5
  Bottom 0.61: LD2.K Q2.C
N$6
  Bottom 0.61: LD3.K Q3.C
N$7  (via drill 1.68)
  Bottom 1.016: C1.1 137.79,87.15 | F1.1A 120.01,80.16
  Bottom 1.27: B1.AC1 140.33,93.18 140.33,89.69 137.79,87.15 | C1.1 133.34,86.51 126.99,80.16 v122.55,80.16 F1.1A
N$8
  Bottom 1.016: 148.27,85.24 CN1.O2 148.03,85.16
  Bottom 1.27: B1.AC2 C1.2 146.68,86.51 148.03,85.16 | CN1.O 151.29,82.22 148.27,85.24
N$9
  Bottom 0.61: LD4.K Q4.C
N$10
  Bottom 0.406: C20.+ 140.58,32.79 140.33,32.54 IC2.2
N$11
  Bottom 0.406: C21.- 127.38,36.28 130.17,33.49 IC2.6
N$12
  Bottom 0.406: C18.+ 137.54,35.97 139.06,34.44 139.06,29.68 140.01,28.73 142.23,28.73 142.87,29.36 IC2.1
N$13
  Bottom 0.406: C18.- 135.5,36.09 137.79,33.81 IC2.3
N$14
  Bottom 0.406: C19.+ 132.46,36.28 135.25,33.49 IC2.4
N$15
  Bottom 0.406: C19.- 130.42,35.78 132.71,33.49 IC2.5
N$16
  Bottom 0.61: LD5.K Q5.C
N$17
  Bottom 0.61: Q16.C 112.07,24.6 R38.1 SV11.3
N$18
  Bottom 0.61: LD6.K Q6.C
N$19
  Bottom 0.61: LD9.K Q9.C
N$20
  Bottom 0.61: LD8.K Q8.C
N$21
  Bottom 0.61: LD7.K Q7.C
N$22
  Bottom 0.61: R18.2 137.16,5.55 LD2.A
N$23
  Bottom 0.61: R19.2 138.74,3.96 129.22,3.96 LD3.A
N$24
  Bottom 0.406: R39.2 99.05,25.55 98.1,24.6 SV12.2
  Bottom 0.61: R39.2 R40.1 | SV12.2 SV11.1
N$25
  Bottom 0.61: LD4.A R20.2
N$26
  Bottom 0.61: LD5.A R21.2
N$27
  Bottom 0.61: LD6.A R22.2
N$28
  Bottom 0.61: LD7.A R23.2
N$29
  Bottom 0.61: LD8.A R24.2
N$30
  Bottom 0.61: LD9.A R25.2
N$31
  Bottom 0.61: LD10.K Q10.C
N$32
  Bottom 0.61: SV3/1.2 68.57,71.27 70.16,72.86 Q4.E Q5.E 85.08,72.86 85.4,72.54 Q6.E Q7.E Q8.E Q9.E
N$33
  Bottom 0.61: LD11.K Q11.C
N$34
  Bottom 0.61: LD12.K Q12.C
N$35
  Bottom 0.61: LD13.K Q13.C
N$36
  Bottom 0.61: LD14.K Q14.C
N$37
  Bottom 0.61: LD11.A R33.2
N$38
  Bottom 0.61: LD12.A R34.2
N$39
  Bottom 0.61: LD13.A R35.2
N$40
  Bottom 0.61: Q10.B 21.58,70 20.95,69.37 R26.2
N$41
  Bottom 0.61: Q11.B 27.3,70 26.66,69.37 26.66,65.56 R27.2
N$42
  Bottom 0.61: Q12.B 33.02,70 32.38,69.37 R28.2
N$43
  Bottom 0.61: Q13.B 38.73,70 38.1,69.37 R29.2
N$44
  Bottom 0.61: LD14.A R36.2
N$45
  Bottom 0.61: LD15.K Q15.C
N$46
  Bottom 0.61: LD15.A R37.2
N$47
  Bottom 0.61: R10.2 Q2.B
N$48
  Bottom 0.406: R38.2 LD16.K
N$49
  Bottom 0.61: Q3.B R11.2
N$50
  Bottom 0.61: Q4.B 70.8,70.32 70.16,69.69 70.16,66.51 71.11,65.56 71.11,60.48 78.73,52.86 99.37,52.86 R12.1
N$51
  Bottom 0.61: R13.1 100.64,54.13 81.59,54.13 77.15,58.57 77.15,65.56 76.19,66.51 76.19,69.37 77.15,70.32 Q5.B
N$52
  Bottom 0.61: Q6.B 83.81,70.32 82.55,69.05 82.55,66.51 83.5,65.56 83.5,59.21 86.99,55.4 104.45,55.4 R14.1
N$53
  Bottom 0.61: R15.1 106.99,55.71 106.04,56.67 92.7,56.67 89.85,59.52 89.85,65.56 88.89,66.51 88.89,69.37 89.85,70.32 Q7.B
N$54
  Bottom 0.61: R16.1 106.99,57.94 98.1,57.94 96.2,59.84 96.2,65.88 95.24,66.83 95.24,69.37 96.52,70.32 Q8.B
N$55
  Bottom 0.61: R5.2 128.58,76.03 LD1.K
N$56
  Bottom 0.61: R17.1 110.48,59.21 103.18,59.21 102.55,59.84 102.55,65.24 101.59,66.19 101.59,69.37 103.18,70.32 Q9.B
N$57
  Bottom 0.61: LD10.A R32.2
N$58
  Bottom 0.61: VR1.C 40,34.44 R2.2 37.46,31.9 C12.1 | R3.1 34.6,34.12 C12.1 | C23.+ 20.95,28.41 21.9,29.36 32.06,29.36 C12.1 | C12.1 34.6,29.36 35.24,28.73 SV14.1
N$59
  Bottom 0.61: Q14.B 44.45,70 43.81,69.37 R30.2
N$60
  Bottom 0.61: Q15.B 50.16,70 49.53,69.37 R31.2
N$61
  Bottom 0.61: Q10.E Q11.E Q12.E Q13.E Q14.E Q15.E 54.61,72.54 58.1,69.05 SV3/2.2
N$62
  Bottom 0.406: IC2.14 137.79,24.92 140.65,27.77 145.73,27.77 147,29.04 X1.2
N$63
  Bottom 0.406: IC2.13 135.25,21.42 135.88,20.79 138.42,20.79 139.06,21.42 139.06,24.92 140.97,26.82 146.36,26.82 X1.3
N$67
  Bottom 0.61: R3.2 29.84,35.39 32.06,37.62 R4.1 42.22,37.62 VR1.R
N$69
  Bottom 0.406: Q16.B 115.88,26.19 113.66,28.41 R39.1
N$73
  Bottom 0.61: SV7.11 66.35,13.81 69.53,16.98 IC1.28
N$74
  Bottom 0.61: SV7.9 66.35,16.34 69.53,19.52 IC1.27
N$75
  Bottom 0.61: SV7.7 66.35,18.88 69.53,22.06 IC1.26
N$76
  Bottom 0.61: IC1.25 69.53,24.6 66.35,21.42 SV7.5
N$77
  Bottom 0.61: SV7.3 65.72,23.96 68.89,27.14 IC1.24
N$78
  Bottom 0.61: IC1.23 69.53,29.68 66.35,26.5 SV7.1
PC0.
  Bottom 0.61: SV1.3 SV1.5 53.34,25.87 SV7.2
PC1.
  Bottom 0.406: SV1.6 42.54,25.55 43.49,24.6 48.57,24.6 49.21,23.96 SV7.4
  Bottom 0.61: SV1.6 SV1.4
PC3.
  Bottom 0.61: S2.1 34.96,22.97 39.05,18.88 SV7.8
PC4.
  Bottom 0.61: S3.1 34.88,14.72 36.51,16.34 SV7.10
PC5.
  Bottom 0.61: S4.1 34.88,6.46 42.22,13.81 SV7.12
PD3
  Bottom 0.61: R13.2 SV8.5 93.97,39.84 92.39,38.25 92.39,34.76 84.77,27.14 IC1.5
PD4
  Bottom 0.61: R14.2 SV8.4 93.66,42.38 90.8,39.52 90.8,35.08 85.4,29.68 IC1.6
PD5
  Bottom 0.61: IC1.11 84.13,47.14 92.07,47.14 94.29,44.92 SV8.3 R15.2
RESET
  Bottom 0.61: 78.77,10.67 78.73,10.63 | 78.77,10.67 S1.2 82.9,10.67 C13.2 84.45,11.27 R7.1 88.89,13.81 89.53,13.17 SV10.3 | IC1.1 79.37,11.27 78.77,10.67
RESET1
  Bottom 0.61: SV4.1 8.89,43.33 6.66,43.33 3.49,40.16 3.49,22.38 21.27,4.6 35.87,4.6 41.91,10.63 72.38,10.63 72.35,10.67 S1.1
RXD
  Bottom 0.61: IC2.12 R10.1 129.85,17.93 101.91,17.93 99.69,15.71 SV10.2 91.44,15.71 87.62,19.52 IC1.2
SCK-RS  (via drill 0.41 pad 1.42)
  Top 0.406: v8.89,70.32 v3.17,70.32
  Bottom 0.406: SV4.4 7.3,51.27 5.39,53.17 5.39,58.89 8.89,62.38 v8.89,70.32 | v3.17,70.32 1.58,71.91 1.58,76.03 2.22,76.67 SV2.4
  Bottom 0.61: 49.53,42.38 52.07,39.84 SV6.1 IC1.19 | 49.53,42.38 R31.1 | SV4.4 12.7,51.27 21.58,42.38 49.53,42.38
SCL
  Bottom 0.61: IC1.12 80.32,44.92 83.81,48.41 93.34,48.41 94.29,47.46 SV8.2 R16.2 SV13.1
SCL1
  Bottom 0.61: SV13.2 120.64,47.46 R9.1 123.5,50.32 SV9.3 IC4.6 139.06,50.32 144.14,55.4 147.63,55.4 148.9,56.67 148.9,59.52 147.95,60.48 IC3.2
SDA
  Bottom 0.61: IC1.13 81.27,47.46 83.81,50 SV8.1 R17.2 SV13.3
SDA1
  Bottom 0.61: SV13.4 R8.1 123.5,52.86 SV9.2 IC4.5 138.74,52.86 143.82,57.94 IC3.1
TXD
  Bottom 0.61: IC2.11 R11.1 129.22,20.15 101.28,20.15 99.37,18.25 SV10.1 92.39,18.25 88.58,22.06 IC1.3
VCC  (via drill 0.41 pad 1.42)
  Top 0.406: v19.04,72.22 v4.44,72.22
  Top 0.61: v19.04,41.43 v19.04,62.7
  Bottom 0.406: 76.51,24.6 76.51,25.87 85.4,25.87 93.66,34.12 93.66,37.62 94.61,38.57 109.21,38.57 LD16.A | 153.03,70.64 153.35,70.64 | 153.03,17.3 152.71,17.3 | SV12.3 92.39,27.14 88.58,23.33 76.51,23.33
  Bottom 0.61: R33.1 R34.1 | R22.1 87.94,76.03 87.62,76.35 | R23.1 94.29,76.03 93.97,76.35 | 147.63,47.78 148.9,46.51 148.9,44.28 147.95,43.33 142.23,43.33 140.33,45.24 | 140.33,45.24 IC4.8 136.52,45.24 133.03,41.74 124.45,41.74 121.6,38.89 121.6,36.98 | 140.33,45.24 142.55,43.02 142.55,37.3 C20.- | C17.1 84.77,32.22 IC1.7 77.78,32.22 76.51,30.95 76.51,25.87 76.51,23.33 76.51,9.36 77.46,8.41 84.77,8.41 R7.2 | C6.1 6.66,36.66 | 152.71,17.3 144.46,17.3 | 153.35,70.64 155.25,68.73 155.25,61.75 C9.1 155.57,57.62 155.57,50 C8.1 | C8.1 155.57,45.87 155.57,19.84 153.03,17.3 | 121.6,36.98 LD16.A 110.48,36.98 106.67,33.17 R40.2 | R19.1 R18.1 | 144.46,17.3 R19.1 | C8.1 147.63,47.78 | 147.63,47.78 IC4.2 | R19.1 142.87,15.39 | 144.46,17.3 142.87,18.88 IC2.16 | 121.6,36.98 C22.1
  Bottom 1.016: R37.1 R36.1 R35.1 R34.1 | R32.1 R33.1 | R32.1 25.71,80.16 16.82,89.05 16.82,92.55 | R20.1 R21.1 87.62,76.35 | R22.1 93.97,76.35 | R23.1 R24.1 R25.1 | R25.1 109.21,74.13 120.64,74.13 | 120.64,74.13 123.5,74.13 126.99,70.64 LD1.A 153.03,70.64 | 6.66,36.66 L1.1 15.24,41.43 v19.04,41.43 12.38,48.73 SV4.3 | 126.99,57.62 R9.2 R8.2 120.64,74.13 | 126.99,57.62 129.22,55.4 SV9.1 133.66,55.4 136.2,57.94 IC3.8 | C7.1 107.63,76.99 R25.1 | R32.1 21.27,76.35 19.04,74.13 v19.04,72.22 v19.04,62.7 | v4.44,72.22 SV2.2 | SV2.15 7.3,91.91 7.93,92.55 16.82,92.55 | 16.82,92.55 R6.E | SV15.2 SV16.2 128.58,63.02 126.99,61.43 126.99,57.62
  Bottom 1.27: C7.1 105.09,81.43 C4.+ 91.12,81.43 87.94,84.61 87.94,88.73 90.8,91.59 IC5.OUT C5.1 | R37.1 R20.1

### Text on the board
Bottom: AVR-Testboard | OE5GHN | JÄNNER 2004 | V1.2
